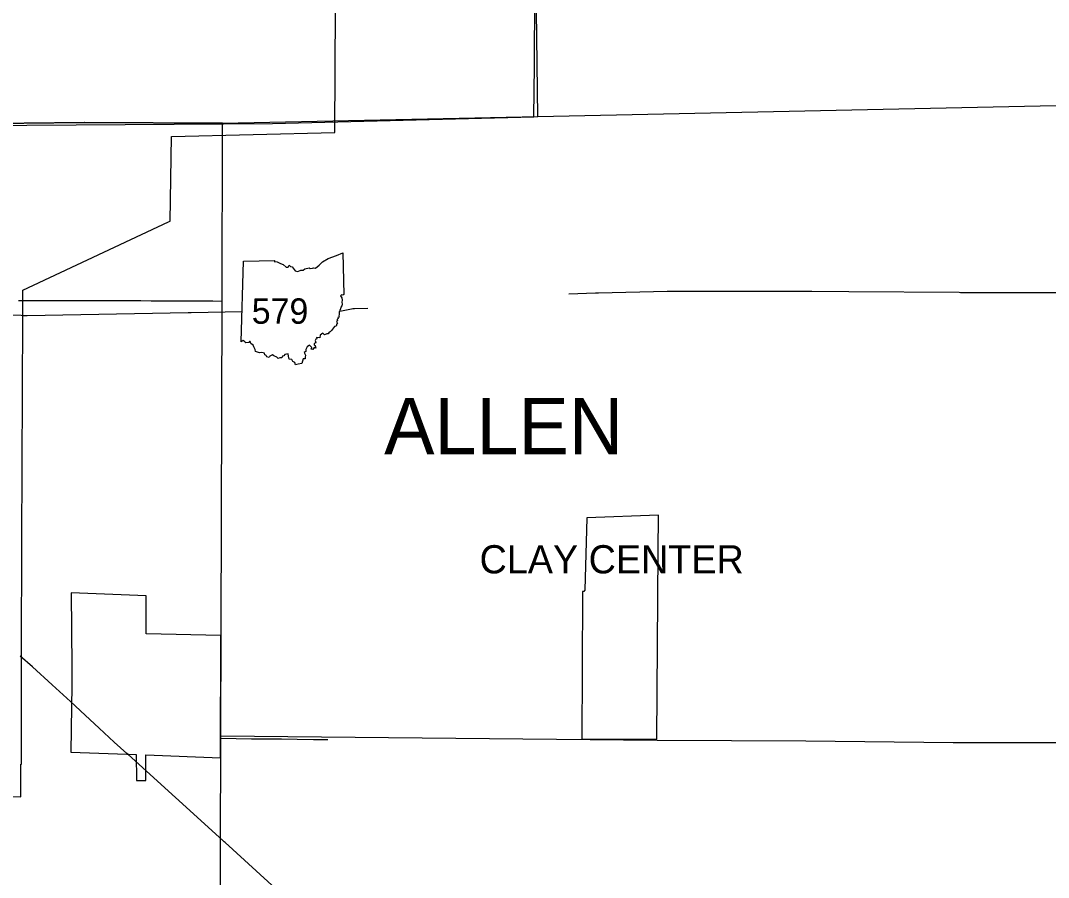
# Model space of a CAD drawing. Extents: x -232 to 448, y 619 to 1059.
# Drawn here: x 201.69 to 239.07, y 890.09 to 921.24 of the extents above; entities that cross this region are included whole.
import ezdxf

# ---------------------------------------------------------------- set-up
doc = ezdxf.new("R2010")
doc.units = 0
doc.layers.add('Default', color=7, linetype='Continuous')

msp = doc.modelspace()

# ---------------------------------------------------------------- linework, layer by layer
at = {"layer": 'Default'}
msp.add_line((209.716, 909.563), (209.798, 912.492), dxfattribs=at)
msp.add_line((209.716, 909.563), (209.798, 912.492), dxfattribs=at)
for points in [[(220.494, 917.745), (220.412, 924.484), (220.44, 929.941), (220.445, 935.396), (220.451, 940.914), (220.461, 942.705)], [(213.121, 917.175), (213.159, 923.975), (213.195, 932.178), (213.198, 937.62), (213.201, 942.169)], [(220.376, 919.589), (220.43, 929.912)], [(220.349, 917.742), (220.376, 919.589)], [(220.494, 917.745), (241.621, 918.197)], [(209.038, 917.513), (220.494, 917.745)], [(210.852, 917.502), (220.349, 917.742)], [(209.038, 917.513), (203.999, 917.529), (204.024, 917.527), (191.897, 917.396), (187.286, 917.38), (185.424, 917.355), (181.851, 917.318), (179.825, 917.331), (178.107, 917.388), (173.34, 917.43)], [(183.856, 917.339), (185.424, 917.355), (187.286, 917.38), (191.897, 917.396), (203.999, 917.529), (209.038, 917.513)], [(200.128, 917.421), (210.852, 917.502)], [(208.972, 895.219), (209.019, 911.042), (209.038, 917.513)], [(209.019, 911.042), (209.038, 917.513)], [(207.136, 913.948), (207.179, 917.026)], [(207.179, 917.026), (213.121, 917.175)], [(201.772, 911.436), (207.07, 913.918), (207.136, 913.948)], [(209.798, 912.492), (210.934, 912.511), (210.916, 912.476), (211.024, 912.468), (211.138, 912.406), (211.234, 912.366), (211.352, 912.273), (211.422, 912.274), (211.452, 912.351), (211.506, 912.292), (211.57, 912.281), (211.681, 912.141), (211.772, 912.111), (211.882, 912.159), (211.964, 912.167), (212.024, 912.214), (212.18, 912.255), (212.223, 912.23), (212.306, 912.235), (212.347, 912.253), (212.419, 912.237), (212.546, 912.344), (212.676, 912.469), (212.877, 912.588), (213.177, 912.7), (213.414, 912.8), (213.448, 911.28)], [(209.798, 912.492), (210.934, 912.511), (210.916, 912.476), (211.024, 912.468), (211.138, 912.406), (211.234, 912.366), (211.352, 912.273), (211.422, 912.274), (211.452, 912.351), (211.506, 912.292), (211.57, 912.281), (211.681, 912.141), (211.772, 912.111), (211.882, 912.159), (211.964, 912.167), (212.024, 912.214), (212.18, 912.255), (212.223, 912.23), (212.306, 912.235), (212.347, 912.253), (212.419, 912.237), (212.546, 912.344), (212.676, 912.469), (212.877, 912.588), (213.177, 912.7), (213.414, 912.8), (213.448, 911.28)], [(201.769, 910.517), (201.769, 910.569), (201.772, 911.436)], [(213.448, 911.28), (213.413, 911.259), (213.359, 911.269), (213.322, 911.227), (213.367, 911.155), (213.389, 911.08), (213.37, 910.997), (213.389, 910.929), (213.376, 910.872), (213.342, 910.815), (213.33, 910.761), (213.301, 910.704), (213.303, 910.672), (213.275, 910.646), (213.28, 910.551), (213.266, 910.499), (213.271, 910.453), (213.226, 910.441), (213.236, 910.404), (213.208, 910.375), (213.214, 910.325), (213.182, 910.293), (213.213, 910.229), (213.188, 910.209), (213.167, 910.131), (213.109, 910.116), (212.993, 909.974), (212.953, 909.92), (212.907, 909.907), (212.882, 909.852), (212.825, 909.852), (212.74, 909.813), (212.685, 909.879), (212.588, 909.8), (212.577, 909.709), (212.455, 909.712), (212.459, 909.665), (212.432, 909.652), (212.407, 909.606), (212.422, 909.524), (212.364, 909.503), (212.371, 909.455), (212.408, 909.426), (212.424, 909.334), (212.363, 909.353), (212.314, 909.276), (212.262, 909.294), (212.279, 909.359), (212.193, 909.438), (212.111, 909.375), (212.068, 909.275), (212.067, 909.207), (212.006, 909.166), (212.046, 909.071), (212.038, 909.006), (212.04, 908.943), (211.963, 908.945), (211.917, 908.777)], [(213.448, 911.28), (213.413, 911.259), (213.359, 911.269), (213.322, 911.227), (213.367, 911.155), (213.389, 911.08), (213.37, 910.997), (213.389, 910.929), (213.376, 910.872), (213.342, 910.815), (213.33, 910.761), (213.301, 910.704), (213.303, 910.672), (213.275, 910.646), (213.28, 910.551), (213.266, 910.499), (213.271, 910.453), (213.226, 910.441), (213.236, 910.404), (213.208, 910.375), (213.214, 910.325), (213.182, 910.293), (213.213, 910.229), (213.188, 910.209), (213.167, 910.131), (213.109, 910.116), (212.993, 909.974), (212.953, 909.92), (212.907, 909.907), (212.882, 909.852), (212.825, 909.852), (212.74, 909.813), (212.685, 909.879), (212.588, 909.8), (212.577, 909.709), (212.455, 909.712), (212.459, 909.665), (212.432, 909.652), (212.407, 909.606), (212.422, 909.524), (212.364, 909.503), (212.371, 909.455), (212.408, 909.426), (212.424, 909.334), (212.363, 909.353), (212.314, 909.276), (212.262, 909.294), (212.279, 909.359), (212.193, 909.438), (212.111, 909.375), (212.068, 909.275), (212.067, 909.207), (212.006, 909.166), (212.046, 909.071), (212.038, 909.006), (212.04, 908.943), (211.963, 908.945), (211.917, 908.777)], [(221.623, 911.305), (222.598, 911.341), (222.63, 911.342), (222.706, 911.344), (225.199, 911.4), (225.209, 911.4), (225.307, 911.4), (228.289, 911.399)], [(228.289, 911.399), (230.348, 911.399), (230.376, 911.399), (230.457, 911.398), (231.812, 911.388)], [(231.812, 911.388), (235.823, 911.359), (235.867, 911.358), (235.931, 911.358), (241.731, 911.356), (241.74, 911.355), (241.784, 911.355)], [(201.614, 911.056), (202.051, 911.056), (202.389, 911.065), (202.834, 911.061), (203.315, 911.058), (203.758, 911.067), (204.219, 911.057), (204.705, 911.056), (205.147, 911.059), (205.641, 911.056), (206.068, 911.059), (206.434, 911.054), (206.906, 911.05), (207.338, 911.048), (207.816, 911.054), (208.303, 911.049), (208.685, 911.053), (209.019, 911.042)], [(201.383, 910.536), (201.718, 910.525)], [(201.718, 910.525), (201.77, 910.521), (201.863, 910.521), (201.934, 910.521), (207.788, 910.624), (207.837, 910.624), (207.896, 910.625), (209.746, 910.659)], [(201.721, 898.361), (201.735, 902.218), (201.735, 902.232), (201.735, 902.323), (201.77, 910.463), (201.769, 910.517)], [(213.303, 910.674), (213.727, 910.758), (213.776, 910.768), (213.834, 910.77), (214.321, 910.788)], [(211.917, 908.777), (211.785, 908.745), (211.692, 908.726), (211.66, 908.802), (211.594, 908.843), (211.551, 908.919), (211.457, 908.93), (211.434, 909.036), (211.424, 909.121), (211.295, 909.1), (211.259, 909.048), (211.213, 909.034), (211.187, 908.981), (211.124, 908.976), (211.057, 908.952), (211.013, 909.003), (210.903, 909.055), (210.854, 909.082), (210.751, 909.04), (210.729, 908.991), (210.646, 909.013), (210.627, 909.068), (210.577, 909.084), (210.566, 909.143), (210.46, 909.174), (210.379, 909.161), (210.235, 909.208), (210.227, 909.285), (210.178, 909.379), (210.152, 909.444), (210.062, 909.493), (210.043, 909.57), (210.014, 909.568), (209.988, 909.537), (209.887, 909.522), (209.847, 909.554), (209.79, 909.608), (209.716, 909.563)], [(211.917, 908.777), (211.785, 908.745), (211.692, 908.726), (211.66, 908.802), (211.594, 908.843), (211.551, 908.919), (211.457, 908.93), (211.434, 909.036), (211.424, 909.121), (211.295, 909.1), (211.259, 909.048), (211.213, 909.034), (211.187, 908.981), (211.124, 908.976), (211.057, 908.952), (211.013, 909.003), (210.903, 909.055), (210.854, 909.082), (210.751, 909.04), (210.729, 908.991), (210.646, 909.013), (210.627, 909.068), (210.577, 909.084), (210.566, 909.143), (210.46, 909.174), (210.379, 909.161), (210.235, 909.208), (210.227, 909.285), (210.178, 909.379), (210.152, 909.444), (210.062, 909.493), (210.043, 909.57), (210.014, 909.568), (209.988, 909.537), (209.887, 909.522), (209.847, 909.554), (209.79, 909.608), (209.716, 909.563)], [(222.285, 903.167), (222.21, 900.529)], [(224.882, 903.26), (222.285, 903.167)], [(224.824, 895.111), (224.874, 901.934), (224.882, 903.26)], [(203.537, 900.437), (203.557, 897.743), (203.55, 897.043), (203.541, 896.297), (203.523, 894.638), (205.898, 894.56)], [(208.973, 898.889), (206.259, 898.949), (206.263, 900.32), (203.537, 900.437)], [(222.21, 900.529), (222.177, 900.482), (222.123, 900.487), (222.108, 897.643)], [(208.965, 894.437), (208.973, 898.889)], [(201.722, 894.617), (201.722, 894.67), (201.721, 898.306), (201.721, 898.361)], [(212.654, 888.167), (211.609, 889.098), (211.598, 889.106), (211.528, 889.17), (209.127, 891.354), (209.1, 891.377), (209.046, 891.427), (205.601, 894.554), (205.559, 894.591), (205.1, 895.001), (204.549, 895.518), (204.046, 895.984), (203.505, 896.481), (202.838, 897.091), (202.123, 897.747), (201.681, 898.128)], [(222.108, 897.643), (222.095, 895.13)], [(208.923, 878.575), (208.972, 895.219)], [(241.234, 894.977), (235.605, 894.982), (230.248, 895.042), (224.835, 895.064), (208.972, 895.219)], [(208.972, 895.152), (209.529, 895.14), (210.094, 895.133), (210.631, 895.129), (211.178, 895.126), (211.745, 895.114), (212.343, 895.107), (212.867, 895.101)], [(222.095, 895.13), (224.824, 895.111)], [(201.706, 894.206), (201.721, 894.205), (201.722, 894.617)], [(205.898, 894.56), (205.901, 893.615), (206.246, 893.612), (206.248, 894.548)], [(206.248, 894.548), (208.965, 894.437)], [(201.701, 893.024), (201.705, 893.978), (201.706, 894.206)], [(196.22, 893.065), (201.701, 893.024)]]:
    msp.add_lwpolyline(points, dxfattribs=at)

# ---------------------------------------------------------------- texts
for s, height, p in [('579', 0.9234, (210.096, 910.216)), ('ALLEN', 2.052, (214.912, 905.471)), ('CLAY CENTER', 1.026, (218.382, 901.141))]:
    msp.add_text(s, height=height, dxfattribs=at).set_placement(p)

doc.saveas('drawing.dxf')
